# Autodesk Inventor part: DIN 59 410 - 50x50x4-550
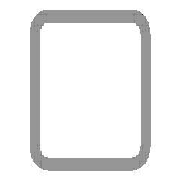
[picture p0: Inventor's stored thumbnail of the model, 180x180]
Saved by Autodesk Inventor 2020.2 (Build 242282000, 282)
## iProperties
Manager: www.cadconsulting.pl
Company: Fabian Stasiak CAD Consulting
Created: 2015-01
Part Number: DIN 59 410 - 50x50x4-550
Material: Stal, miękka
Description: Rurki stalowe o przekroju kwadratowym formowane na gorąco
Document SubType Name: Modellieren
Standard: DIN
Designer: F.Stasiak
Standards Organization: DIN
Language: pl-PL
Size Designation: 50x50x4
Categories: <MemberInstance><Categories><Category DisplayName="Kształtowniki konstrukcyjne" InternalName="089c4875-fa83-4c05-b084-43b9cc11f5ed" Mnemonic="GRDR"><CategoryPar
Stock Number: 50x50x4
Density: 7.85 g/cm^3
Appearance: Częściowo polerowana
Mass: 2999.78 g
Surface Area: 1924.59 cm^2
Volume: 382.138 cm^3
Catalog Web Link: www.expertbooks.pl
_CCFamilyMember: 40
_CCFamilyDisplayName: DIN 59410 (Kwadrat) - Rurki stalowe o przekroju kwadratowym formowane na gorąco
_FrameMemberDoc: Frame Member File
_Version: 15.0.0
_GetPNFromCC: 1
G_W: 50,000 mm
G_H: 50,000 mm
+D8030832-D18D-4216-8516-9693604CAF99+CUTDETAIL1: Wytnij
+9FAC0B3A-763A-49AB-A06F-535DBBFE4FDA+CUTDETAIL2: Wytnij
G_L: 550,000 mm
IsCustomPart: 1
Author: F.Stasiak
Subject: Zbiór ćwiczeń. Autodesk Inventor 2020. Kurs Professional
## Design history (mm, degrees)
node "Płaszczyzna początkowa"
node "Płaszczyzna końcowa"
sketch "Szkic"
  geometry: L1 (-17, 25)-(17, 25); L2 (25, 17)-(25, -17); L3 (17, -25)-(-17, -25); L4 (-25, -17)-(-25, 17); L5 (-37.32, 0)-(37.32, 0) reference; L6 (0, -37.32)-(0, 37.32) reference; L7 (-17, 21)-(17, 21); L8 (21, 17)-(21, -17); L9 (17, -21)-(-17, -21); L10 (-21, -17)-(-21, 17); A1 r 8 centre (-17, 17) between (-17, 25) and (-25, 17); A2 r 8 centre (17, 17) between (25, 17) and (17, 25); A3 r 8 centre (17, -17) between (17, -25) and (25, -17); A4 r 8 centre (-17, -17) between (-25, -17) and (-17, -25); A5 r 4 centre (-17, 17) between (-17, 21) and (-21, 17); A6 r 4 centre (17, 17) between (21, 17) and (17, 21); A7 r 4 centre (17, -17) between (17, -21) and (21, -17); A8 r 4 centre (-17, -17) between (-21, -17) and (-17, -21); 3 further points
  constraints: 16 end point, 16 point on circle, 8 centre point, 8 tangent, 6 point on line, 4 parallel, 3 equal radius, 3 perpendicular, 1 horizontal, 7 other
  dimensions: "b" = 50 distance of point (-25, 25) point (25, 25); "msp_r" = 8 radius of A1 (= 2 x ParT); "d8" = 25 distance between parallel lines of L4 L6 (= d9); "d9" = 25 distance between parallel lines of L3 L5 (= 0.5 x b); "d10" = 4 distance between parallel lines of L3 L9 (= ParT)
extrude "Bryła" new body sketch "Szkic" taper "d4" = 0 deg; stored distance "NLG" = 10
node "Driven Length"
  sketch "Sketch2"
    geometry: L1 (0, 0)-(10, 0) reference
    constraints: 2 end point, 1 horizontal
  workplane "Work Plane3"
  sketch "Sketch3"
    geometry: L1 (-2, 25)-(12, 25) reference; L2 (-2, 575)-(12, 575) reference
    dimensions: "d14" = 550 distance between parallel lines of L1 L2 (derived)
node "Płaszczyzna konstrukcyjna4"
feature "Podział1"
node "Płaszczyzna konstrukcyjna5"
feature "Podział2"
body "Solid1"
other parameters: "ParT" = 4, "G_OFFSET_START" = -25 [user parameter; used in 1 equation term], "G_OFFSET_END" = -25 [user parameter; used in 1 equation term], "d11" = 25 (= -G_OFFSET_START), "d12" = 575 (= G_OFFSET_END + B_L), "G_L" = 550 (= d14) [user parameter], "d13" = 90 deg
